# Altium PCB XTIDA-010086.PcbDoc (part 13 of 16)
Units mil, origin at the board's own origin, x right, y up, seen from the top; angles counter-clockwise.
Board outline 14763.78 x 8267.72 mil, 6 copper layers (Top Layer, GND Layer, Signal Layer 1, Signal Layer 2, Power Layer, Bottom Layer), stack 62 mil thick; 1933 components, 1002 nets, 4886 pads, 6482 vias.
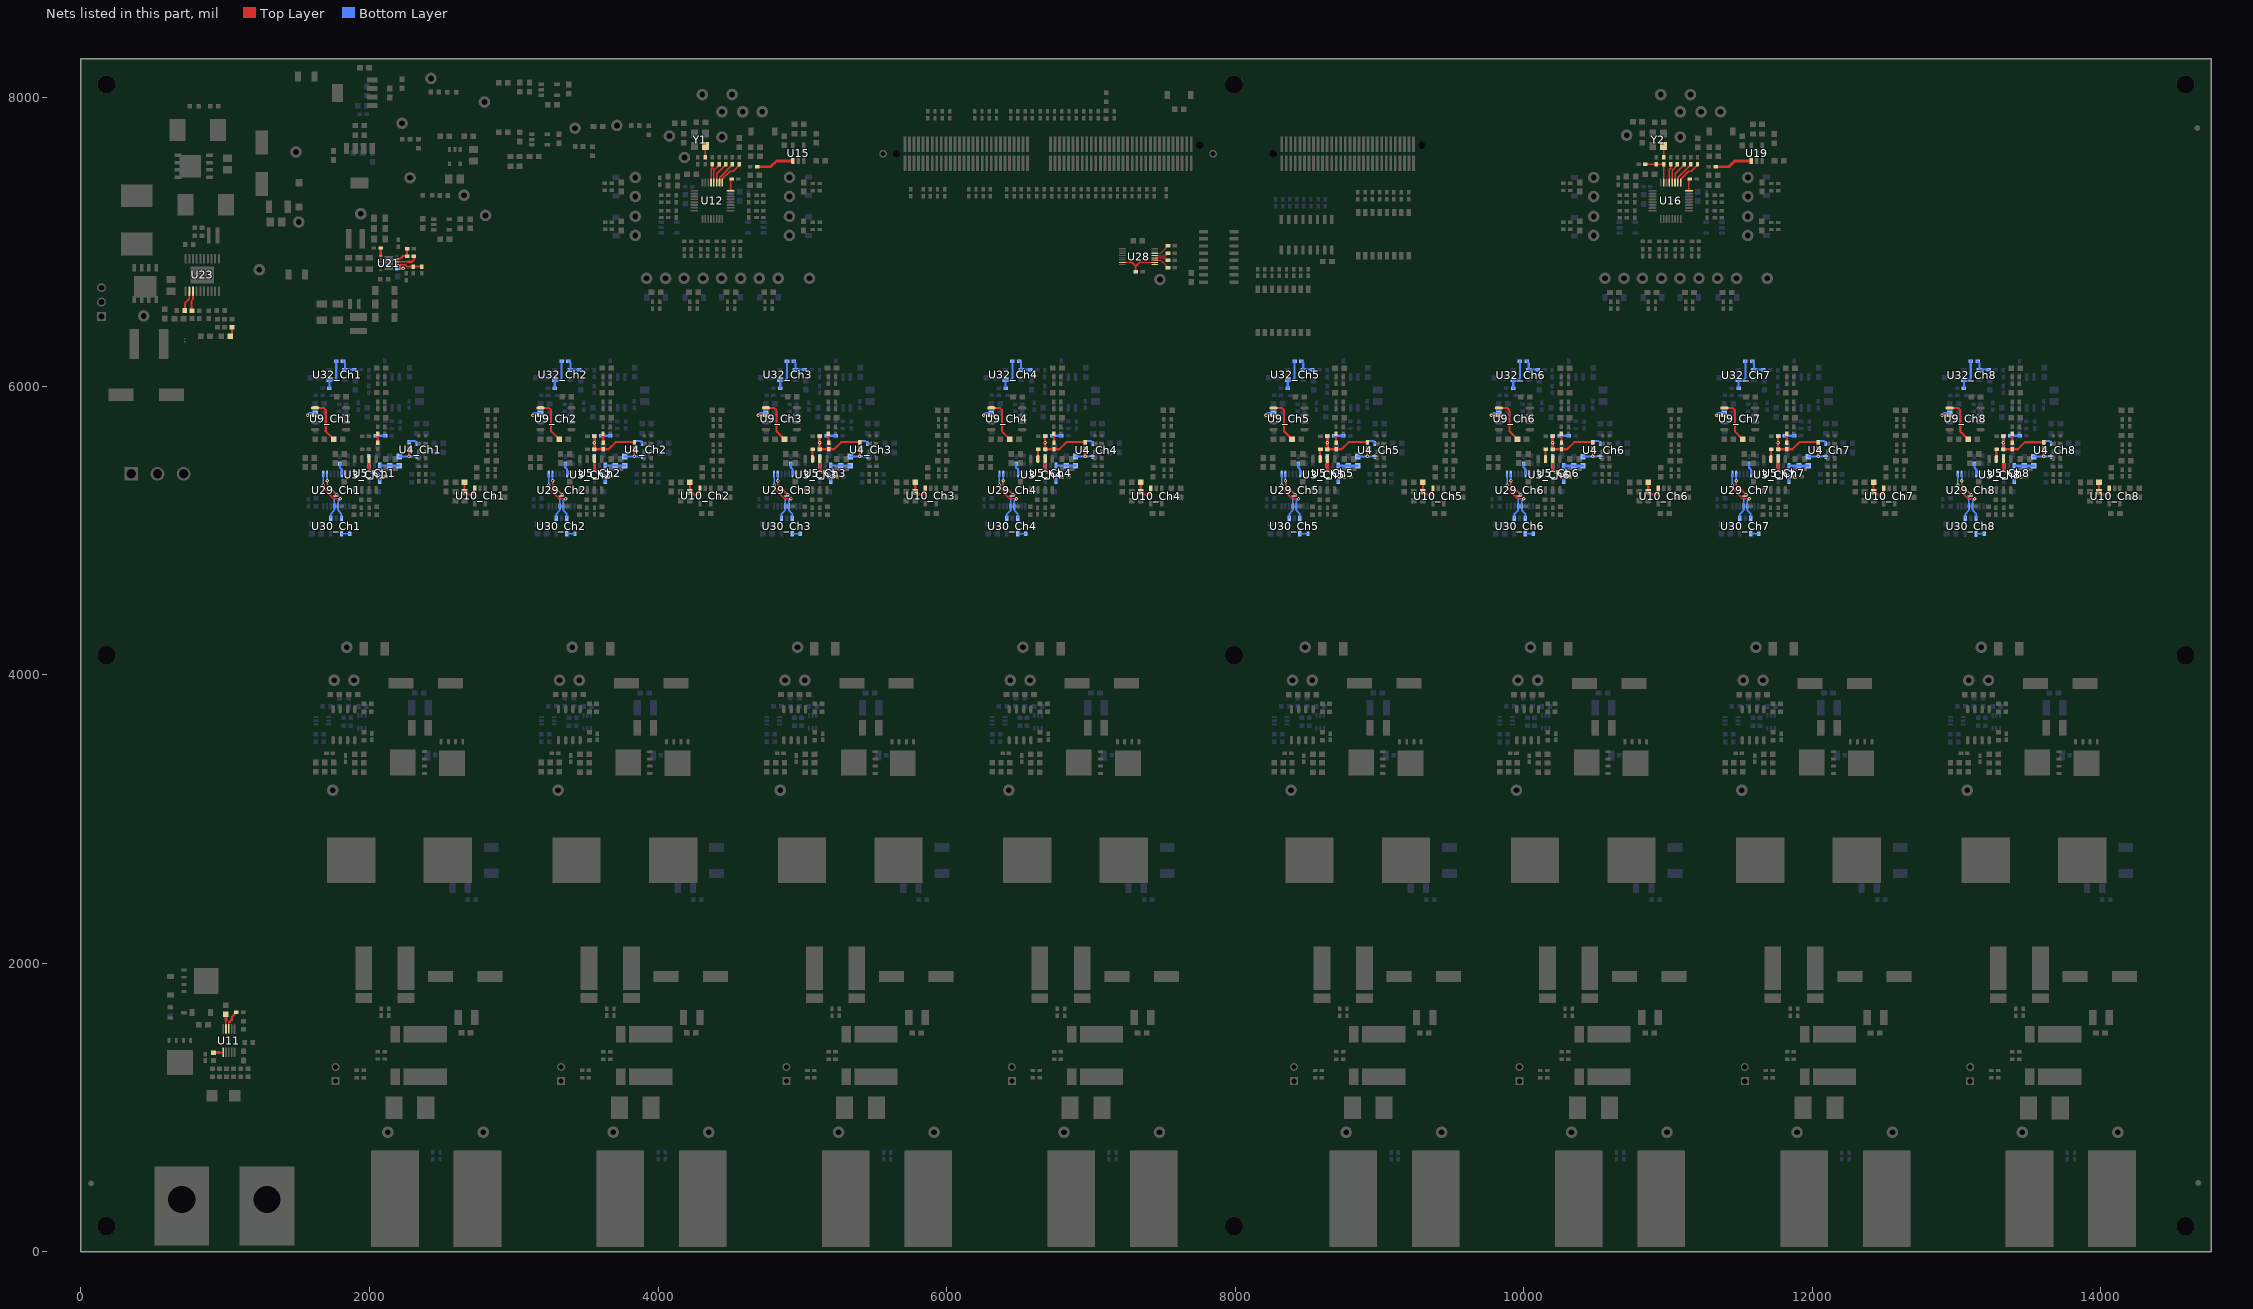
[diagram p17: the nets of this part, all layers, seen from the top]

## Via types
v1: diameter 32, hole 16, Top Layer to Bottom Layer, tented both sides, 4685 vias
v2: diameter 24, hole 12, Top Layer to Bottom Layer, tented both sides, 1013 vias
v3: diameter 32, hole 16, Top Layer to Bottom Layer, 728 vias
v4: diameter 19.68, hole 7.87, Top Layer to Bottom Layer, 40 vias
v5: diameter 214.57, hole 140, Top Layer to Bottom Layer, 16 vias

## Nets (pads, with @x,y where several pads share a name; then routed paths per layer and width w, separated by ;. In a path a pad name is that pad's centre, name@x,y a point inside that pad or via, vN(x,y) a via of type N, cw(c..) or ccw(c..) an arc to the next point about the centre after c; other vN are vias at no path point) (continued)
NetR31_Ch2_2: R31_Ch2.2 R32_Ch2.1 R41_Ch2.1 R43_Ch2.1 R48_Ch2.1 R175_Ch2.2 | length 484.6
  Top Layer w15: R31_Ch2.2@3558.62,5561.97 v2(3558.62,5607.62) R175_Ch2.2@3558.62,5653.28 ; R31_Ch2.2@3558.62,5561.97 3657.45,5562 3707.04,5611.59 R41_Ch2.1@3837,5611.59
  Bottom Layer w15: R43_Ch2.1@3558.62,5561.97 v2(3558.62,5607.62) 3558.62,5655.21 R48_Ch2.1@3559.38,5655.97
NetR31_Ch3_1: R31_Ch3.1 U3_Ch3.7 | length 68.7
  Top Layer w15: U3_Ch3.7@5071,5494.17 5071,5559.51 R31_Ch3.1@5073.38,5561.89
NetR31_Ch3_2: R31_Ch3.2 R32_Ch3.1 R41_Ch3.1 R43_Ch3.1 R48_Ch3.1 R175_Ch3.2 | length 481.4
  Top Layer w15: R175_Ch3.2@5120.62,5653.2 v2(5120.62,5607.54) R31_Ch3.2@5120.62,5561.89 5215.42,5561.89 ; R32_Ch3.1@5181.38,5561.89 R32_Ch3.1@5182,5561.27 ; 5219.45,5561.92 5269.04,5611.51 R41_Ch3.1@5399,5611.51
  Bottom Layer w15: R43_Ch3.1@5120.62,5561.89 v2(5120.62,5607.54) 5120.62,5655.13 R48_Ch3.1@5121.38,5655.89
NetR31_Ch4_1: R31_Ch4.1 U3_Ch4.7 | length 68.7
  Top Layer w15: U3_Ch4.7@6633,5494.09 6633,5559.43 R31_Ch4.1@6635.38,5561.81
NetR31_Ch4_2: R31_Ch4.2 R32_Ch4.1 R41_Ch4.1 R43_Ch4.1 R48_Ch4.1 R175_Ch4.2 | length 481.4
  Top Layer w15: R175_Ch4.2@6682.62,5653.12 v2(6682.62,5607.46) R31_Ch4.2@6682.62,5561.81 6777.42,5561.81 ; R32_Ch4.1@6743.38,5561.81 R32_Ch4.1@6744,5561.19 ; 6781.45,5561.84 6831.04,5611.43 R41_Ch4.1@6961,5611.43
  Bottom Layer w15: R43_Ch4.1@6682.62,5561.81 v2(6682.62,5607.46) 6682.62,5655.06 R48_Ch4.1@6683.38,5655.81
NetR31_Ch5_1: R31_Ch5.1 U3_Ch5.7 | length 68.7
  Top Layer w15: U3_Ch5.7@8588.7,5494.02 8588.7,5559.35 R31_Ch5.1@8591.08,5561.73
NetR31_Ch5_2: R31_Ch5.2 R32_Ch5.1 R41_Ch5.1 R43_Ch5.1 R48_Ch5.1 R175_Ch5.2 | length 481.4
  Top Layer w15: R175_Ch5.2@8638.32,5653.04 v2(8638.32,5607.39) R31_Ch5.2@8638.32,5561.73 8733.12,5561.73 ; R32_Ch5.1@8699.08,5561.73 R32_Ch5.1@8699.7,5561.11 ; 8737.15,5561.76 8786.74,5611.35 R41_Ch5.1@8916.7,5611.35
  Bottom Layer w15: R43_Ch5.1@8638.32,5561.73 v2(8638.32,5607.39) 8638.32,5654.98 R48_Ch5.1@8639.08,5655.73
NetR31_Ch6_1: R31_Ch6.1 U3_Ch6.7 | length 68.7
  Top Layer w15: U3_Ch6.7@10150.7,5493.94 10150.7,5559.28 R31_Ch6.1@10153.08,5561.65
NetR31_Ch6_2: R31_Ch6.2 R32_Ch6.1 R41_Ch6.1 R43_Ch6.1 R48_Ch6.1 R175_Ch6.2 | length 481.4
  Top Layer w15: R175_Ch6.2@10200.32,5652.96 v2(10200.32,5607.31) R31_Ch6.2@10200.32,5561.65 10295.12,5561.65 ; R32_Ch6.1@10261.08,5561.65 R32_Ch6.1@10261.7,5561.03 ; 10299.15,5561.68 10348.74,5611.28 R41_Ch6.1@10478.7,5611.28
  Bottom Layer w15: R43_Ch6.1@10200.32,5561.65 v2(10200.32,5607.31) 10200.32,5654.9 R48_Ch6.1@10201.08,5655.65
NetR31_Ch7_1: R31_Ch7.1 U3_Ch7.7 | length 68.7
  Top Layer w15: U3_Ch7.7@11712.7,5493.86 11712.7,5559.2 R31_Ch7.1@11715.08,5561.57
NetR31_Ch7_2: R31_Ch7.2 R32_Ch7.1 R41_Ch7.1 R43_Ch7.1 R48_Ch7.1 R175_Ch7.2 | length 481.4
  Top Layer w15: R175_Ch7.2@11762.32,5652.88 v2(11762.32,5607.23) R31_Ch7.2@11762.32,5561.57 11857.12,5561.57 ; R32_Ch7.1@11823.08,5561.57 R32_Ch7.1@11823.7,5560.95 ; 11861.15,5561.6 11910.74,5611.2 R41_Ch7.1@12040.7,5611.2
  Bottom Layer w15: R43_Ch7.1@11762.32,5561.57 v2(11762.32,5607.23) 11762.32,5654.82 R48_Ch7.1@11763.08,5655.57
NetR31_Ch8_1: R31_Ch8.1 U3_Ch8.7 | length 68.7
  Top Layer w15: U3_Ch8.7@13274.7,5493.78 13274.7,5559.12 R31_Ch8.1@13277.08,5561.5
NetR31_Ch8_2: R31_Ch8.2 R32_Ch8.1 R41_Ch8.1 R43_Ch8.1 R48_Ch8.1 R175_Ch8.2 | length 481.4
  Top Layer w15: R175_Ch8.2@13324.32,5652.8 v2(13324.32,5607.15) R31_Ch8.2@13324.32,5561.5 13419.12,5561.5 ; R32_Ch8.1@13385.08,5561.5 R32_Ch8.1@13385.7,5560.87 ; 13423.15,5561.52 13472.74,5611.12 R41_Ch8.1@13602.7,5611.12
  Bottom Layer w15: R43_Ch8.1@13324.32,5561.5 v2(13324.32,5607.15) 13324.32,5654.74 R48_Ch8.1@13325.08,5655.5
NetR32_Ch1_2: R32_Ch1.2 R33_Ch1.1 | length 62.2
  Top Layer w15: R33_Ch1.1@2057,5670.43 2058,5669.43 R32_Ch1.2@2058,5608.67
NetR32_Ch2_2: R32_Ch2.2 R33_Ch2.1 | length 62.2
  Top Layer w15: R33_Ch2.1@3619,5670.35 3620,5669.35 R32_Ch2.2@3620,5608.59
NetR32_Ch3_2: R32_Ch3.2 R33_Ch3.1 | length 62.2
  Top Layer w15: R33_Ch3.1@5181,5670.27 5182,5669.27 R32_Ch3.2@5182,5608.51
NetR32_Ch4_2: R32_Ch4.2 R33_Ch4.1 | length 62.2
  Top Layer w15: R33_Ch4.1@6743,5670.19 6744,5669.19 R32_Ch4.2@6744,5608.43
NetR32_Ch5_2: R32_Ch5.2 R33_Ch5.1 | length 62.2
  Top Layer w15: R33_Ch5.1@8698.7,5670.11 8699.7,5669.11 R32_Ch5.2@8699.7,5608.35
NetR32_Ch6_2: R32_Ch6.2 R33_Ch6.1 | length 62.2
  Top Layer w15: R33_Ch6.1@10260.7,5670.03 10261.7,5669.03 R32_Ch6.2@10261.7,5608.28
NetR32_Ch7_2: R32_Ch7.2 R33_Ch7.1 | length 62.2
  Top Layer w15: R33_Ch7.1@11822.7,5669.95 11823.7,5668.95 R32_Ch7.2@11823.7,5608.2
NetR32_Ch8_2: R32_Ch8.2 R33_Ch8.1 | length 62.2
  Top Layer w15: R33_Ch8.1@13384.7,5669.87 13385.7,5668.87 R32_Ch8.2@13385.7,5608.12
NetR41_Ch1_2: R41_Ch1.2 R44_Ch1.1 U4_Ch1.6 | length 171.1
  Top Layer w15: v2(2275,5513.28) R41_Ch1.2@2275,5564.43
  Bottom Layer w15: R44_Ch1.1@2207,5511.54 2325.2,5511.54 U4_Ch1.6@2326.41,5512.76
NetR41_Ch2_2: R41_Ch2.2 R44_Ch2.1 U4_Ch2.6 | length 171.1
  Top Layer w15: v2(3837,5513.21) R41_Ch2.2@3837,5564.35
  Bottom Layer w15: R44_Ch2.1@3769,5511.46 3887.2,5511.46 U4_Ch2.6@3888.41,5512.68
NetR41_Ch3_2: R41_Ch3.2 R44_Ch3.1 U4_Ch3.6 | length 171.1
  Top Layer w15: v2(5399,5513.13) R41_Ch3.2@5399,5564.27
  Bottom Layer w15: R44_Ch3.1@5331,5511.39 5449.2,5511.39 U4_Ch3.6@5450.41,5512.6
NetR41_Ch4_2: R41_Ch4.2 R44_Ch4.1 U4_Ch4.6 | length 171.1
  Top Layer w15: v2(6961,5513.05) R41_Ch4.2@6961,5564.19
  Bottom Layer w15: R44_Ch4.1@6893,5511.31 7011.2,5511.31 U4_Ch4.6@7012.41,5512.52
NetR41_Ch5_2: R41_Ch5.2 R44_Ch5.1 U4_Ch5.6 | length 171.1
  Top Layer w15: v2(8916.7,5512.97) R41_Ch5.2@8916.7,5564.11
  Bottom Layer w15: R44_Ch5.1@8848.7,5511.23 8966.9,5511.23 U4_Ch5.6@8968.11,5512.44
NetR41_Ch6_2: R41_Ch6.2 R44_Ch6.1 U4_Ch6.6 | length 171.1
  Top Layer w15: v2(10478.7,5512.89) R41_Ch6.2@10478.7,5564.03
  Bottom Layer w15: R44_Ch6.1@10410.7,5511.15 10528.9,5511.15 U4_Ch6.6@10530.11,5512.36
NetR41_Ch7_2: R41_Ch7.2 R44_Ch7.1 U4_Ch7.6 | length 171.1
  Top Layer w15: v2(12040.7,5512.81) R41_Ch7.2@12040.7,5563.95
  Bottom Layer w15: R44_Ch7.1@11972.7,5511.07 12090.9,5511.07 U4_Ch7.6@12092.11,5512.28
NetR41_Ch8_2: R41_Ch8.2 R44_Ch8.1 U4_Ch8.6 | length 171.1
  Top Layer w15: v2(13602.7,5512.73) R41_Ch8.2@13602.7,5563.87
  Bottom Layer w15: R44_Ch8.1@13534.7,5510.99 13652.9,5510.99 U4_Ch8.6@13654.11,5512.2
NetR42_1: R42.1 U28.7 U28.9 U28.10 | length 300.5
  Top Layer w6: U28.7@7218,6857.02 7261.44,6857.02 ; 7361.32,6857.02 U28.10@7442.41,6857.02 U28.9@7442.41,6841.27
  Top Layer w10: 7261.44,6857.02 7283.99,6857.02 7311.38,6829.63 ; R42.1@7311.38,6792.01 7311.38,6829.63 ; 7361.32,6857.02 7338.76,6857.02 7311.38,6829.63
NetR43_Ch1_2: R43_Ch1.2 U5_Ch1.1 U5_Ch1.4 | length 231.5
  Bottom Layer w15: R43_Ch1.2@1996.62,5514.8 1997.6,5513.83 U5_Ch1.1@1997.6,5449.18 1997.6,5413.08 2009.98,5400.7 2054.72,5400.7 2072.4,5383.02 U5_Ch1.4@2072.4,5340.91
NetR43_Ch2_2: R43_Ch2.2 U5_Ch2.1 U5_Ch2.4 | length 231.5
  Bottom Layer w15: R43_Ch2.2@3558.62,5514.72 3559.6,5513.75 U5_Ch2.1@3559.6,5449.1 3559.6,5413 3571.98,5400.62 3616.72,5400.62 3634.4,5382.94 U5_Ch2.4@3634.4,5340.83
NetR43_Ch3_2: R43_Ch3.2 U5_Ch3.1 U5_Ch3.4 | length 231.5
  Bottom Layer w15: R43_Ch3.2@5120.62,5514.65 5121.6,5513.67 U5_Ch3.1@5121.6,5449.02 5121.6,5412.92 5133.98,5400.54 5178.72,5400.54 5196.4,5382.87 U5_Ch3.4@5196.4,5340.76
NetR43_Ch4_2: R43_Ch4.2 U5_Ch4.1 U5_Ch4.4 | length 231.5
  Bottom Layer w15: R43_Ch4.2@6682.62,5514.57 6683.6,5513.59 U5_Ch4.1@6683.6,5448.94 6683.6,5412.84 6695.98,5400.46 6740.72,5400.46 6758.4,5382.79 U5_Ch4.4@6758.4,5340.68
NetR43_Ch5_2: R43_Ch5.2 U5_Ch5.1 U5_Ch5.4 | length 231.5
  Bottom Layer w15: R43_Ch5.2@8638.32,5514.49 8639.3,5513.51 U5_Ch5.1@8639.3,5448.87 8639.3,5412.76 8651.68,5400.39 8696.42,5400.39 8714.1,5382.71 U5_Ch5.4@8714.1,5340.6
NetR43_Ch6_2: R43_Ch6.2 U5_Ch6.1 U5_Ch6.4 | length 231.5
  Bottom Layer w15: R43_Ch6.2@10200.32,5514.41 10201.3,5513.43 U5_Ch6.1@10201.3,5448.79 10201.3,5412.69 10213.68,5400.31 10258.42,5400.31 10276.1,5382.63 U5_Ch6.4@10276.1,5340.52
NetR43_Ch7_2: R43_Ch7.2 U5_Ch7.1 U5_Ch7.4 | length 231.5
  Bottom Layer w15: R43_Ch7.2@11762.32,5514.33 11763.3,5513.35 11763.3,5412.61 11775.68,5400.23 11820.42,5400.23 11838.1,5382.55 U5_Ch7.4@11838.1,5340.44
NetR43_Ch8_2: R43_Ch8.2 U5_Ch8.1 U5_Ch8.4 | length 231.5
  Bottom Layer w15: R43_Ch8.2@13324.32,5514.25 13325.3,5513.28 13325.3,5412.53 13337.68,5400.15 13382.42,5400.15 13400.1,5382.47 U5_Ch8.4@13400.1,5340.36
NetR44_Ch1_2: R44_Ch1.2 R46_Ch1.2 U5_Ch1.3 | length 134.9
  Bottom Layer w15: U5_Ch1.3@2072.4,5449.18 2073.03,5448.55 R46_Ch1.2@2142,5448.55 R44_Ch1.2@2207,5448.55
NetR44_Ch2_2: R44_Ch2.2 R46_Ch2.2 U5_Ch2.3 | length 134.9
  Bottom Layer w15: U5_Ch2.3@3634.4,5449.1 3635.03,5448.47 R46_Ch2.2@3704,5448.47 R44_Ch2.2@3769,5448.47
NetR44_Ch3_2: R44_Ch3.2 R46_Ch3.2 U5_Ch3.3 | length 134.9
  Bottom Layer w15: U5_Ch3.3@5196.4,5449.02 5197.03,5448.39 R46_Ch3.2@5266,5448.39 R44_Ch3.2@5331,5448.39
NetR44_Ch4_2: R44_Ch4.2 R46_Ch4.2 U5_Ch4.3 | length 134.9
  Bottom Layer w15: U5_Ch4.3@6758.4,5448.94 6759.03,5448.32 R46_Ch4.2@6828,5448.32 R44_Ch4.2@6893,5448.32
NetR44_Ch5_2: R44_Ch5.2 R46_Ch5.2 U5_Ch5.3 | length 134.9
  Bottom Layer w15: U5_Ch5.3@8714.1,5448.87 8714.73,5448.24 R46_Ch5.2@8783.7,5448.24 R44_Ch5.2@8848.7,5448.24
NetR44_Ch6_2: R44_Ch6.2 R46_Ch6.2 U5_Ch6.3 | length 134.9
  Bottom Layer w15: U5_Ch6.3@10276.1,5448.79 10276.73,5448.16 R46_Ch6.2@10345.7,5448.16 R44_Ch6.2@10410.7,5448.16
NetR44_Ch7_2: R44_Ch7.2 R46_Ch7.2 U5_Ch7.3 | length 134.9
  Bottom Layer w15: U5_Ch7.3@11838.1,5448.71 11838.73,5448.08 R46_Ch7.2@11907.7,5448.08 R44_Ch7.2@11972.7,5448.08
NetR44_Ch8_2: R44_Ch8.2 R46_Ch8.2 U5_Ch8.3 | length 134.9
  Bottom Layer w15: U5_Ch8.3@13400.1,5448.63 13400.73,5448 R46_Ch8.2@13469.7,5448 R44_Ch8.2@13534.7,5448
NetR48_Ch1_2: R48_Ch1.2 R52_Ch1.1 | length 63.8
  Bottom Layer w15: R48_Ch1.2@2044.62,5656.05 R52_Ch1.1@2108.38,5656.05
NetR48_Ch2_2: R48_Ch2.2 R52_Ch2.1 | length 63.8
  Bottom Layer w15: R48_Ch2.2@3606.62,5655.97 R52_Ch2.1@3670.38,5655.97
NetR48_Ch3_2: R48_Ch3.2 R52_Ch3.1 | length 63.8
  Bottom Layer w15: R48_Ch3.2@5168.62,5655.89 R52_Ch3.1@5232.38,5655.89
NetR48_Ch4_2: R48_Ch4.2 R52_Ch4.1 | length 63.8
  Bottom Layer w15: R48_Ch4.2@6730.62,5655.81 R52_Ch4.1@6794.38,5655.81
NetR48_Ch5_2: R48_Ch5.2 R52_Ch5.1 | length 63.8
  Bottom Layer w15: R48_Ch5.2@8686.32,5655.73 R52_Ch5.1@8750.08,5655.73
NetR48_Ch6_2: R48_Ch6.2 R52_Ch6.1 | length 63.8
  Bottom Layer w15: R48_Ch6.2@10248.32,5655.65 R52_Ch6.1@10312.08,5655.65
NetR48_Ch7_2: R48_Ch7.2 R52_Ch7.1 | length 63.8
  Bottom Layer w15: R48_Ch7.2@11810.32,5655.57 R52_Ch7.1@11874.08,5655.57
NetR48_Ch8_2: R48_Ch8.2 R52_Ch8.1 | length 63.8
  Bottom Layer w15: R48_Ch8.2@13372.32,5655.5 R52_Ch8.1@13436.08,5655.5
NetR49_Ch1_1: R49_Ch1.1 U4_Ch1.1 | length 64.9
  Bottom Layer w15: R49_Ch1.1@2275,5611.67 2282.03,5618.7 2314.79,5618.7 2326.41,5607.08 U4_Ch1.1@2326.41,5601.34
NetR49_Ch2_1: R49_Ch2.1 U4_Ch2.1 | length 64.9
  Bottom Layer w15: R49_Ch2.1@3837,5611.59 3844.03,5618.62 3876.79,5618.62 3888.41,5607 U4_Ch2.1@3888.41,5601.26
NetR49_Ch3_1: R49_Ch3.1 U4_Ch3.1 | length 64.9
  Bottom Layer w15: R49_Ch3.1@5399,5611.51 5406.03,5618.54 5438.79,5618.54 5450.41,5606.92 U4_Ch3.1@5450.41,5601.18
NetR49_Ch4_1: R49_Ch4.1 U4_Ch4.1 | length 64.9
  Bottom Layer w15: R49_Ch4.1@6961,5611.43 6968.03,5618.46 7000.79,5618.46 7012.41,5606.84 U4_Ch4.1@7012.41,5601.1
NetR49_Ch5_1: R49_Ch5.1 U4_Ch5.1 | length 64.9
  Bottom Layer w15: R49_Ch5.1@8916.7,5611.35 8923.73,5618.39 8956.49,5618.39 8968.11,5606.76 U4_Ch5.1@8968.11,5601.02
NetR49_Ch6_1: R49_Ch6.1 U4_Ch6.1 | length 64.9
  Bottom Layer w15: R49_Ch6.1@10478.7,5611.28 10485.73,5618.31 10518.49,5618.31 10530.11,5606.69 U4_Ch6.1@10530.11,5600.94
NetR49_Ch7_1: R49_Ch7.1 U4_Ch7.1 | length 64.9
  Bottom Layer w15: R49_Ch7.1@12040.7,5611.2 12047.73,5618.23 12080.49,5618.23 12092.11,5606.61 U4_Ch7.1@12092.11,5600.87
NetR49_Ch8_1: R49_Ch8.1 U4_Ch8.1 | length 64.9
  Bottom Layer w15: R49_Ch8.1@13602.7,5611.12 13609.73,5618.15 13642.49,5618.15 13654.11,5606.53 U4_Ch8.1@13654.11,5600.79
NetR54_1: R54.1 U28.14 | length 113.1
  Top Layer w6: U28.14@7442.41,6920.01 7483.38,6920.01 R54.1@7534.38,6971.01
NetR55_1: R55.1 U28.13 | length 98.9
  Top Layer w6: U28.13@7442.41,6904.26 7517.63,6904.26 R55.1@7534.38,6921.01
NetR56_1: R56.1 U28.12 | length 99.2
  Top Layer w6: U28.12@7442.41,6888.52 7516.87,6888.52 R56.1@7534.38,6871.01
NetR57_1: R57.1 U28.11 | length 113.4
  Top Layer w6: U28.11@7442.41,6872.77 7482.62,6872.77 R57.1@7534.38,6821.01
NetR63_Ch1_1: R63_Ch1.1 R64_Ch1.2 U10_Ch1.3 | length 182
  Top Layer w15: R63_Ch1.1@2659.04,5332.68 R64_Ch1.2@2659.04,5268.3 2667.02,5268.3 2687.18,5248.14 2720.47,5248.14 2729.14,5256.82 U10_Ch1.3@2729.14,5292.43
NetR63_Ch2_1: R63_Ch2.1 R64_Ch2.2 U10_Ch2.3 | length 182
  Top Layer w15: R63_Ch2.1@4221.04,5332.6 R64_Ch2.2@4221.04,5268.22 4229.02,5268.22 4249.18,5248.06 4282.47,5248.06 4291.14,5256.74 U10_Ch2.3@4291.14,5292.35
NetR63_Ch3_1: R63_Ch3.1 R64_Ch3.2 U10_Ch3.3 | length 182
  Top Layer w15: R63_Ch3.1@5783.04,5332.52 R64_Ch3.2@5783.04,5268.14 5791.02,5268.14 5811.18,5247.98 5844.47,5247.98 5853.14,5256.66 U10_Ch3.3@5853.14,5292.28
NetR63_Ch4_1: R63_Ch4.1 R64_Ch4.2 U10_Ch4.3 | length 182
  Top Layer w15: R63_Ch4.1@7345.04,5332.44 R64_Ch4.2@7345.04,5268.06 7353.02,5268.06 7373.18,5247.91 7406.47,5247.91 7415.14,5256.58 U10_Ch4.3@7415.14,5292.2
NetR63_Ch5_1: R63_Ch5.1 R64_Ch5.2 U10_Ch5.3 | length 182
  Top Layer w15: R63_Ch5.1@9300.74,5332.36 R64_Ch5.2@9300.74,5267.98 9308.72,5267.98 9328.88,5247.83 9362.17,5247.83 9370.84,5256.5 U10_Ch5.3@9370.84,5292.12
NetR63_Ch6_1: R63_Ch6.1 R64_Ch6.2 U10_Ch6.3 | length 182
  Top Layer w15: R63_Ch6.1@10862.74,5332.28 R64_Ch6.2@10862.74,5267.91 10870.72,5267.91 10890.88,5247.75 10924.17,5247.75 10932.84,5256.42 U10_Ch6.3@10932.84,5292.04
NetR63_Ch7_1: R63_Ch7.1 R64_Ch7.2 U10_Ch7.3 | length 182
  Top Layer w15: R63_Ch7.1@12424.74,5332.2 R64_Ch7.2@12424.74,5267.83 12432.72,5267.83 12452.88,5247.67 12486.17,5247.67 12494.84,5256.34 U10_Ch7.3@12494.84,5291.96
NetR63_Ch8_1: R63_Ch8.1 R64_Ch8.2 U10_Ch8.3 | length 182
  Top Layer w15: R63_Ch8.1@13986.74,5332.13 R64_Ch8.2@13986.74,5267.75 13994.72,5267.75 14014.88,5247.59 14048.17,5247.59 14056.84,5256.26 U10_Ch8.3@14056.84,5291.88
NetR75_Ch1_2: R75_Ch1.2 U9_Ch1.5 | length 305.1
  Top Layer w15: U9_Ch1.5@1623.72,5848.55 1681.61,5848.55 1697,5833.16 1697,5686.2 R75_Ch1.2@1752.5,5630.7
NetR75_Ch2_2: R75_Ch2.2 U9_Ch2.5 | length 305.1
  Top Layer w15: U9_Ch2.5@3185.72,5848.47 3243.61,5848.47 3259,5833.08 3259,5686.13 R75_Ch2.2@3314.5,5630.62
NetR75_Ch3_2: R75_Ch3.2 U9_Ch3.5 | length 305.1
  Top Layer w15: U9_Ch3.5@4747.72,5848.39 4805.61,5848.39 4821,5833 4821,5686.05 R75_Ch3.2@4876.5,5630.54
NetR75_Ch4_2: R75_Ch4.2 U9_Ch4.5 | length 305.1
  Top Layer w15: U9_Ch4.5@6309.72,5848.31 6367.61,5848.31 6383,5832.92 6383,5685.97 R75_Ch4.2@6438.5,5630.46
NetR75_Ch5_2: R75_Ch5.2 U9_Ch5.5 | length 305.1
  Top Layer w15: U9_Ch5.5@8265.42,5848.24 8323.31,5848.24 8338.7,5832.84 8338.7,5685.89 R75_Ch5.2@8394.2,5630.39
NetR75_Ch6_2: R75_Ch6.2 U9_Ch6.5 | length 305.1
  Top Layer w15: U9_Ch6.5@9827.42,5848.16 9885.31,5848.16 9900.7,5832.76 9900.7,5685.81 R75_Ch6.2@9956.2,5630.31
NetR75_Ch7_2: R75_Ch7.2 U9_Ch7.5 | length 305.1
  Top Layer w15: U9_Ch7.5@11389.42,5848.08 11447.31,5848.08 11462.7,5832.69 11462.7,5685.73 R75_Ch7.2@11518.2,5630.23
NetR75_Ch8_2: R75_Ch8.2 U9_Ch8.5 | length 305.1
  Top Layer w15: U9_Ch8.5@12951.42,5848 13009.31,5848 13024.7,5832.61 13024.7,5685.65 R75_Ch8.2@13080.2,5630.15
NetR78_Ch1_1: R78_Ch1.1 U9_Ch1.6 | length 111.1
  Top Layer w15: v2(1571.15,5798.55) U9_Ch1.6@1623.72,5798.55
  Bottom Layer w15: v2(1571.15,5798.55) 1585.63,5813.03 R78_Ch1.1@1623.72,5813.03
NetR78_Ch2_1: R78_Ch2.1 U9_Ch2.6 | length 111.1
  Top Layer w15: v2(3133.15,5798.47) U9_Ch2.6@3185.72,5798.47
  Bottom Layer w15: v2(3133.15,5798.47) 3147.63,5812.95 R78_Ch2.1@3185.72,5812.95
NetR78_Ch3_1: R78_Ch3.1 U9_Ch3.6 | length 111.1
  Top Layer w15: v2(4695.15,5798.39) U9_Ch3.6@4747.72,5798.39
  Bottom Layer w15: v2(4695.15,5798.39) 4709.63,5812.87 R78_Ch3.1@4747.72,5812.87
NetR78_Ch4_1: R78_Ch4.1 U9_Ch4.6 | length 111.1
  Top Layer w15: v2(6257.15,5798.31) U9_Ch4.6@6309.72,5798.31
  Bottom Layer w15: v2(6257.15,5798.31) 6271.63,5812.79 R78_Ch4.1@6309.72,5812.79
NetR78_Ch5_1: R78_Ch5.1 U9_Ch5.6 | length 111.1
  Top Layer w15: v2(8212.85,5798.24) U9_Ch5.6@8265.42,5798.24
  Bottom Layer w15: v2(8212.85,5798.24) 8227.33,5812.71 R78_Ch5.1@8265.42,5812.71
NetR78_Ch6_1: R78_Ch6.1 U9_Ch6.6 | length 111.1
  Top Layer w15: v2(9774.85,5798.16) U9_Ch6.6@9827.42,5798.16
  Bottom Layer w15: v2(9774.85,5798.16) 9789.33,5812.63 R78_Ch6.1@9827.42,5812.63
NetR78_Ch7_1: R78_Ch7.1 U9_Ch7.6 | length 111.1
  Top Layer w15: v2(11336.85,5798.08) U9_Ch7.6@11389.42,5798.08
  Bottom Layer w15: v2(11336.85,5798.08) 11351.33,5812.55 R78_Ch7.1@11389.42,5812.55
NetR78_Ch8_1: R78_Ch8.1 U9_Ch8.6 | length 111.1
  Top Layer w15: v2(12898.85,5798) U9_Ch8.6@12951.42,5798
  Bottom Layer w15: v2(12898.85,5798) 12913.33,5812.48 R78_Ch8.1@12951.42,5812.48
NetR82_2: R82.2 U11.1 | length 67.4
  Top Layer w10: 961.37,1381.12 984.01,1381.12 U11.1@985.96,1383.07
  Top Layer w20: R82.2@919.33,1381.12 961.37,1381.12
NetR83_1: R83.1 U11.9 | length 101.3
  Top Layer w10: U11.9@1005.65,1544.48 1005.65,1604
  Top Layer w20: R83.1@1005,1645.5 1005.65,1644.86 1005.65,1604
NetR86_1: R86.1 U11.8 | length 136.1
  Top Layer w10: U11.8@1025.33,1544.48 1025.33,1588.04 1032.14,1594.86
  Top Layer w15: 1032.14,1594.86 1047.14,1609.86 1047.14,1628.77 R86.1@1077.38,1659
NetR97_2: R97.2 Y1.3 | length 78.2
  Top Layer w10: R97.2@4328.11,7584.63 4328.11,7662.3 Y1.3@4328.52,7662.7
NetR102_1: R102.1 U12.21 | length 131.1
  Top Layer w10: U12.21@4367.27,7410 4367.27,7501.38 4376.11,7510.22 R102.1@4376.11,7537.39
NetR105_1: R105.1 U12.20 | length 142.4
  Top Layer w10: U12.20@4386.96,7410 4386.96,7495.79 4423.11,7531.94 R105.1@4423.11,7537.39
NetR106_1: R106.1 U12.19 | length 153.3
  Top Layer w10: U12.19@4406.64,7410 4406.64,7471.54 4469.11,7534.01 R106.1@4469.11,7537.39
NetR110_1: R110.1 U12.18 | length 164.2
  Top Layer w10: U12.18@4426.33,7410 4426.33,7444.43 4515.11,7533.22 R110.1@4515.11,7537.39
NetR112_1: R112.1 U12.17 | length 187.2
  Top Layer w10: U12.17@4446.01,7410 4446.01,7435.12 4500.53,7489.63 4520.53,7489.63 4562.11,7531.22 R112.1@4562.11,7537.39
NetR114_1: R114.1 U12.16 | length 84.8
  Top Layer w10: U12.16@4503.1,7352.91 4503.1,7428.62 R114.1@4509.49,7435.01
NetR120_1: R120.1 U15.1 | length 263.9
  Top Layer w20: R120.1@4687.74,7520.01 4779.91,7520.01 4820.24,7560.35 U15.1@4934.93,7560.35
NetR126_1: R126.1 R128.1 R187.1 U16.23 | length 254.8
  Top Layer w10: R187.1@10842.62,7536.86 10842.83,7537.08 R126.1@10916.82,7537.08 R128.1@10969.82,7537.08 10969.6,7536.86 U16.23@10969.6,7409.68
NetR128_2: R128.2 Y2.3 | length 78.2
  Top Layer w10: R128.2@10969.82,7584.32 10969.82,7661.99 Y2.3@10970.22,7662.39
NetR133_1: R133.1 U16.21 | length 131.1
  Top Layer w10: U16.21@11008.97,7409.68 11008.97,7501.06 11017.82,7509.91 R133.1@11017.82,7537.08
NetR136_1: R136.1 U16.20 | length 142.4
  Top Layer w10: U16.20@11028.66,7409.68 11028.66,7495.47 11064.82,7531.63 R136.1@11064.82,7537.08
NetR137_1: R137.1 U16.19 | length 153.3
  Top Layer w10: U16.19@11048.34,7409.68 11048.34,7471.22 11110.82,7533.7 R137.1@11110.82,7537.08
NetR141_1: R141.1 U16.18 | length 164.2
  Top Layer w10: U16.18@11068.03,7409.68 11068.03,7444.12 11156.82,7532.91 R141.1@11156.82,7537.08
NetR143_1: R143.1 U16.17 | length 187.2
  Top Layer w10: U16.17@11087.71,7409.68 11087.71,7434.8 11142.23,7489.32 11162.23,7489.32 11203.82,7530.91 R143.1@11203.82,7537.08
NetR145_1: R145.1 U16.16 | length 84.8
  Top Layer w10: U16.16@11144.8,7352.59 11144.8,7428.3 R145.1@11151.19,7434.7
NetR151_1: R151.1 U19.1 | length 264
  Top Layer w20: R151.1@11329.44,7519.7 11421.61,7519.7 11461.94,7560.03 U19.1@11576.63,7560.03
NetR160_Ch1_1: R160_Ch1.1 U30_Ch1.4 | length 56.8
  Bottom Layer w10: U30_Ch1.4@1806.4,4975.87 1862.49,4975.87 R160_Ch1.1@1863,4976.38
NetR160_Ch2_1: R160_Ch2.1 U30_Ch2.4 | length 56.8
  Bottom Layer w10: U30_Ch2.4@3368.4,4975.79 R160_Ch2.1@3424.49,4975.79 R160_Ch2.1@3425,4976.3
NetR160_Ch3_1: R160_Ch3.1 U30_Ch3.4 | length 56.8
  Bottom Layer w10: U30_Ch3.4@4930.4,4975.71 R160_Ch3.1@4986.49,4975.71 R160_Ch3.1@4987,4976.22
NetR160_Ch4_1: R160_Ch4.1 U30_Ch4.4 | length 56.8
  Bottom Layer w10: U30_Ch4.4@6492.4,4975.63 6548.49,4975.63 R160_Ch4.1@6549,4976.14
NetR160_Ch5_1: R160_Ch5.1 U30_Ch5.4 | length 56.8
  Bottom Layer w10: U30_Ch5.4@8448.1,4975.55 8504.19,4975.55 R160_Ch5.1@8504.7,4976.06
NetR160_Ch6_1: R160_Ch6.1 U30_Ch6.4 | length 56.8
  Bottom Layer w10: U30_Ch6.4@10010.1,4975.47 10066.19,4975.47 R160_Ch6.1@10066.7,4975.98
NetR160_Ch7_1: R160_Ch7.1 U30_Ch7.4 | length 56.8
  Bottom Layer w10: U30_Ch7.4@11572.1,4975.39 11628.19,4975.39 R160_Ch7.1@11628.7,4975.91
NetR160_Ch8_1: R160_Ch8.1 U30_Ch8.4 | length 56.8
  Bottom Layer w10: U30_Ch8.4@13134.1,4975.32 R160_Ch8.1@13190.19,4975.32 R160_Ch8.1@13190.7,4975.83
NetR161_Ch1_2: R161_Ch1.2 U29_Ch1.6 | length 76.2
  Bottom Layer w15: R161_Ch1.2@1795.38,5462 1795.38,5435.62 1808.39,5422.61 U29_Ch1.6@1808.39,5391.2
NetR161_Ch2_2: R161_Ch2.2 U29_Ch2.6 | length 76.2
  Bottom Layer w15: R161_Ch2.2@3357.38,5461.92 3357.38,5435.54 3370.39,5422.54 U29_Ch2.6@3370.39,5391.13
NetR161_Ch3_2: R161_Ch3.2 U29_Ch3.6 | length 76.2
  Bottom Layer w15: R161_Ch3.2@4919.38,5461.84 4919.38,5435.46 4932.39,5422.46 U29_Ch3.6@4932.39,5391.05
NetR161_Ch4_2: R161_Ch4.2 U29_Ch4.6 | length 76.2
  Bottom Layer w15: R161_Ch4.2@6481.38,5461.76 6481.38,5435.39 6494.39,5422.38 U29_Ch4.6@6494.39,5390.97
NetR161_Ch5_2: R161_Ch5.2 U29_Ch5.6 | length 76.2
  Bottom Layer w15: R161_Ch5.2@8437.08,5461.69 8437.08,5435.31 8450.09,5422.3 U29_Ch5.6@8450.09,5390.89
NetR161_Ch6_2: R161_Ch6.2 U29_Ch6.6 | length 76.2
  Bottom Layer w15: R161_Ch6.2@9999.08,5461.61 9999.08,5435.23 10012.09,5422.22 U29_Ch6.6@10012.09,5390.81
NetR161_Ch7_2: R161_Ch7.2 U29_Ch7.6 | length 76.2
  Bottom Layer w15: R161_Ch7.2@11561.08,5461.53 11561.08,5435.15 11574.09,5422.14 U29_Ch7.6@11574.09,5390.73
NetR161_Ch8_2: R161_Ch8.2 U29_Ch8.6 | length 76.2
  Bottom Layer w15: R161_Ch8.2@13123.08,5461.45 13123.08,5435.07 13136.09,5422.06 U29_Ch8.6@13136.09,5390.65
NetR185_Ch1_2: R185_Ch1.2 U3_Ch1.6 | length 203.7
  Top Layer w20: U3_Ch1.6@1997,5494.33 1997,5429 2053,5373 R185_Ch1.2@2112.17,5373
NetR185_Ch2_2: R185_Ch2.2 U3_Ch2.6 | length 203.7
  Top Layer w20: U3_Ch2.6@3559,5494.25 3559,5428.92 3615,5372.92 R185_Ch2.2@3674.17,5372.92
NetR185_Ch3_2: R185_Ch3.2 U3_Ch3.6 | length 203.7
  Top Layer w20: U3_Ch3.6@5121,5494.17 5121,5428.84 5177,5372.84 R185_Ch3.2@5236.17,5372.84
NetR185_Ch4_2: R185_Ch4.2 U3_Ch4.6 | length 203.7
  Top Layer w20: U3_Ch4.6@6683,5494.09 6683,5428.76 6739,5372.76 R185_Ch4.2@6798.17,5372.76
NetR185_Ch5_2: R185_Ch5.2 U3_Ch5.6 | length 203.7
  Top Layer w20: U3_Ch5.6@8638.7,5494.02 8638.7,5428.69 8694.7,5372.69 R185_Ch5.2@8753.87,5372.69
NetR185_Ch6_2: R185_Ch6.2 U3_Ch6.6 | length 203.7
  Top Layer w20: U3_Ch6.6@10200.7,5493.94 10200.7,5428.61 10256.7,5372.61 R185_Ch6.2@10315.87,5372.61
NetR185_Ch7_2: R185_Ch7.2 U3_Ch7.6 | length 203.7
  Top Layer w20: U3_Ch7.6@11762.7,5493.86 11762.7,5428.53 11818.7,5372.53 R185_Ch7.2@11877.87,5372.53
NetR185_Ch8_2: R185_Ch8.2 U3_Ch8.6 | length 203.7
  Top Layer w20: U3_Ch8.6@13324.7,5493.78 13324.7,5428.45 13380.7,5372.45 R185_Ch8.2@13439.87,5372.45
NetR195_2: R195.2 U21.2 | length 90.1
  Top Layer w10: U21.2@2189.12,6822.46 2211.28,6822.46 2218.74,6815 v2(2235,6815)
  Bottom Layer w15: R195.2@2197,6822.5 2204.5,6815 v2(2235,6815)
NetR196_2: R196.2 U21.7 | length 55.5
  Top Layer w15: U21.7@2078.62,6901.46 R196.2@2078.62,6957
NetR197_1: R197.1 R199.2 U21.5 | length 130.3
  Top Layer w10: U21.5@2189.12,6881.51 2213.51,6881.51 2224,6892
  Top Layer w15: 2224,6892 2233,6901 R197.1@2261.38,6901 R199.2@2261.38,6951
NetR197_2: R197.2 U21.4 | length 150.6
  Top Layer w10: U21.4@2189.12,6861.83 2268,6861.83
  Top Layer w15: 2268,6861.83 2294.83,6861.83 2308.62,6875.62 R197.2@2308.62,6901
NetR204_Ch1_1: R204_Ch1.1 R219_Ch1.1 U32_Ch1.1 | length 227.6
  Bottom Layer w15: R219_Ch1.1@1722.62,5985 1722.62,6039.08 U32_Ch1.1@1721.87,6039.83 1754.83,6039.83 1769.62,6054.62 R204_Ch1.1@1769.62,6173.24
NetR204_Ch1_2: R204_Ch1.2 R218_Ch1.1 U32_Ch1.4 | length 127.3
  Bottom Layer w15: R204_Ch1.2@1816.87,6173.24 1830.13,6159.97 U32_Ch1.4@1830.13,6114.64 R218_Ch1.1@1893.35,6114.64
NetR204_Ch2_1: R204_Ch2.1 R219_Ch2.1 U32_Ch2.1 | length 227.6
  Bottom Layer w15: R219_Ch2.1@3284.87,5984.68 3284.87,6038.76 U32_Ch2.1@3284.11,6039.51 3317.08,6039.51 3331.87,6054.3 R204_Ch2.1@3331.87,6172.91
NetR204_Ch2_2: R204_Ch2.2 R218_Ch2.1 U32_Ch2.4 | length 127.3
  Bottom Layer w15: R204_Ch2.2@3379.11,6172.91 3392.38,6159.65 U32_Ch2.4@3392.38,6114.31 R218_Ch2.1@3455.6,6114.31
NetR204_Ch3_1: R204_Ch3.1 R219_Ch3.1 U32_Ch3.1 | length 227.6
  Bottom Layer w15: R219_Ch3.1@4846.87,5984.6 4846.87,6038.68 4846.11,6039.43 4879.08,6039.43 4893.87,6054.22 R204_Ch3.1@4893.87,6172.83
NetR204_Ch3_2: R204_Ch3.2 R218_Ch3.1 U32_Ch3.4 | length 127.3
  Bottom Layer w15: R204_Ch3.2@4939.22,6173.31 4952.49,6160.04 U32_Ch3.4@4952.49,6114.71 R218_Ch3.1@5015.71,6114.71
NetR204_Ch4_1: R204_Ch4.1 R219_Ch4.1 U32_Ch4.1 | length 227.6
  Bottom Layer w15: R219_Ch4.1@6408.87,5984.52 6408.87,6038.6 U32_Ch4.1@6408.11,6039.35 6441.08,6039.35 6455.87,6054.14 R204_Ch4.1@6455.87,6172.76
NetR204_Ch4_2: R204_Ch4.2 R218_Ch4.1 U32_Ch4.4 | length 127.3
  Bottom Layer w15: R204_Ch4.2@6503.11,6172.76 6516.38,6159.49 U32_Ch4.4@6516.38,6114.16 R218_Ch4.1@6579.6,6114.16
NetR204_Ch5_1: R204_Ch5.1 R219_Ch5.1 U32_Ch5.1 | length 227.6
  Bottom Layer w15: R219_Ch5.1@8364.57,5984.44 8364.57,6038.52 U32_Ch5.1@8363.81,6039.28 8396.78,6039.28 8411.57,6054.06 R204_Ch5.1@8411.57,6172.68
NetR204_Ch5_2: R204_Ch5.2 R218_Ch5.1 U32_Ch5.4 | length 127.4
  Bottom Layer w15: R204_Ch5.2@8458.81,6172.68 8472.08,6159.41 U32_Ch5.4@8472.08,6114.08 R218_Ch5.1@8535.38,6114 R218_Ch5.1@8535.38,6114
NetR204_Ch6_1: R204_Ch6.1 R219_Ch6.1 U32_Ch6.1 | length 227.6
  Bottom Layer w15: R219_Ch6.1@9926.57,5984.36 U32_Ch6.1@9926.57,6038.44 9925.81,6039.2 9958.78,6039.2 9973.57,6053.98 R204_Ch6.1@9973.57,6172.6
NetR204_Ch6_2: R204_Ch6.2 R218_Ch6.1 U32_Ch6.4 | length 127.4
  Bottom Layer w15: R204_Ch6.2@10020.81,6172.6 10034.08,6159.33 10034.08,6114 10097.3,6114 R218_Ch6.1@10097.38,6113.92
NetR204_Ch7_1: R204_Ch7.1 R219_Ch7.1 U32_Ch7.1 | length 227.6
  Bottom Layer w15: R219_Ch7.1@11488.57,5984.28 11488.57,6038.36 U32_Ch7.1@11487.81,6039.12 11520.78,6039.12 11535.57,6053.91 R204_Ch7.1@11535.57,6172.52
NetR204_Ch7_2: R204_Ch7.2 R218_Ch7.1 U32_Ch7.4 | length 127.4
  Bottom Layer w15: R204_Ch7.2@11582.81,6172.52 11596.08,6159.25 U32_Ch7.4@11596.08,6113.92 R218_Ch7.1@11659.3,6113.92 R218_Ch7.1@11659.38,6113.84
NetR204_Ch8_1: R204_Ch8.1 R219_Ch8.1 U32_Ch8.1 | length 227.6
  Bottom Layer w15: R219_Ch8.1@13050.57,5984.2 13050.57,6038.28 U32_Ch8.1@13049.81,6039.04 13082.78,6039.04 13097.57,6053.83 R204_Ch8.1@13097.57,6172.44
NetR204_Ch8_2: R204_Ch8.2 R218_Ch8.1 U32_Ch8.4 | length 127.4
  Bottom Layer w15: R204_Ch8.2@13144.81,6172.44 13158.08,6159.17 U32_Ch8.4@13158.08,6113.84 R218_Ch8.1@13221.3,6113.84 R218_Ch8.1@13221.38,6113.76
NetR206_2: R206.2 U23.2 | length 145.6
  Top Layer w12: R206.2@721.06,6524.7 721.06,6573.45 751.94,6604.32 U23.2@751.94,6657.5
NetR210_2: R210.2 U23.3 | length 152.2
  Top Layer w12: R210.2@771.3,6523.46 777.53,6529.69 766.54,6529.69 766.54,6590.81 777.53,6601.8 U23.3@777.53,6657.5
NetR214_2: R214.2 R215.1 | length 67.8
  Top Layer w15: R214.2@1035,6345.7 1047.5,6358.2 R215.1@1047.5,6408.34
NetU29_Ch1_1: U29_Ch1.1 U29_Ch1.12 U30_Ch1.3 | length 396.8
  Top Layer w10: v2(1681,5314) 1681,5291 1753,5219 v2(1797,5219)
  Bottom Layer w10: U29_Ch1.1@1680.43,5391.2 1680.43,5314.57 v2(1681,5314) ; v2(1797,5219) 1782.8,5204.8 U29_Ch1.12@1782.8,5166.8 1782.8,5138.2 1806.4,5114.6 U30_Ch1.3@1806.4,5084.13
NetU29_Ch1_2: U29_Ch1.2 U29_Ch1.13 U30_Ch1.1 | length 353.6
  Top Layer w10: v2(1707,5344) 1707,5314 v2(1775,5246)
  Bottom Layer w10: U29_Ch1.2@1706.02,5391.2 1706.02,5344.98 v2(1707,5344) ; U30_Ch1.1@1731.6,5084.13 1731.6,5112.6 1757.2,5138.2 U29_Ch1.13@1757.2,5166.8 1757.2,5228.2 v2(1775,5246)
NetU29_Ch2_1: U29_Ch2.1 U29_Ch2.12 U30_Ch2.3 | length 397.9
  Top Layer w10: v2(3243,5313.92) 3243,5290.92 3315,5218.92 v2(3359,5218.92)
  Bottom Layer w10: U29_Ch2.1@3242.43,5391.13 3242.43,5314.49 v2(3243,5313.92) ; U29_Ch2.12@3344.02,5165.94 U29_Ch2.12@3344.8,5166.72 ; v2(3359,5218.92) 3344.8,5204.72 U29_Ch2.12@3344.8,5166.72 ; U30_Ch2.3@3368.4,5084.06 3368.4,5114.52 3344.8,5138.13 U29_Ch2.12@3344.8,5166.72
NetU29_Ch2_2: U29_Ch2.2 U29_Ch2.13 U30_Ch2.1 | length 353.6
  Top Layer w10: v2(3269,5343.92) 3269,5313.92 v2(3337,5245.92)
  Bottom Layer w10: U29_Ch2.2@3268.02,5391.13 3268.02,5344.9 v2(3269,5343.92) ; U30_Ch2.1@3293.6,5084.06 3293.6,5112.52 3319.2,5138.13 U29_Ch2.13@3319.2,5166.72 3319.2,5228.13 v2(3337,5245.92)
NetU29_Ch3_1: U29_Ch3.1 U29_Ch3.12 U30_Ch3.3 | length 397.9
  Top Layer w10: v2(4805,5313.84) 4805,5290.84 4877,5218.84 v2(4921,5218.84)
  Bottom Layer w10: U29_Ch3.1@4804.43,5391.05 4804.43,5314.41 v2(4805,5313.84) ; U29_Ch3.12@4906.02,5165.87 U29_Ch3.12@4906.8,5166.64 ; v2(4921,5218.84) 4906.8,5204.64 U29_Ch3.12@4906.8,5166.64 ; U30_Ch3.3@4930.4,5083.98 4930.4,5114.44 4906.8,5138.05 U29_Ch3.12@4906.8,5166.64
NetU29_Ch3_2: U29_Ch3.2 U29_Ch3.13 U30_Ch3.1 | length 353.6
  Top Layer w10: v2(4831,5343.84) 4831,5313.84 v2(4899,5245.84)
  Bottom Layer w10: U29_Ch3.2@4830.02,5391.05 4830.02,5344.82 v2(4831,5343.84) ; U30_Ch3.1@4855.6,5083.98 4855.6,5112.44 4881.2,5138.05 U29_Ch3.13@4881.2,5166.64 4881.2,5228.05 v2(4899,5245.84)
NetU29_Ch4_1: U29_Ch4.1 U29_Ch4.12 U30_Ch4.3 | length 397.9
  Top Layer w10: v2(6367,5313.76) 6367,5290.76 6439,5218.76 v2(6483,5218.76)
  Bottom Layer w10: U29_Ch4.1@6366.43,5390.97 6366.43,5314.33 v2(6367,5313.76) ; U29_Ch4.12@6468.02,5165.79 U29_Ch4.12@6468.8,5166.56 ; v2(6483,5218.76) 6468.8,5204.56 U29_Ch4.12@6468.8,5166.56 ; U30_Ch4.3@6492.4,5083.9 6492.4,5114.36 6468.8,5137.97 U29_Ch4.12@6468.8,5166.56
NetU29_Ch4_2: U29_Ch4.2 U29_Ch4.13 U30_Ch4.1 | length 353.6
  Top Layer w10: v2(6393,5343.76) 6393,5313.76 v2(6461,5245.76)
  Bottom Layer w10: U29_Ch4.2@6392.02,5390.97 6392.02,5344.74 v2(6393,5343.76) ; U30_Ch4.1@6417.6,5083.9 6417.6,5112.36 6443.2,5137.97 U29_Ch4.13@6443.2,5166.56 6443.2,5227.97 v2(6461,5245.76)
NetU29_Ch5_1: U29_Ch5.1 U29_Ch5.12 U30_Ch5.3 | length 397.9
  Top Layer w10: v2(8322.7,5313.69) 8322.7,5290.69 8394.7,5218.69 v2(8438.7,5218.69)
  Bottom Layer w10: U29_Ch5.1@8322.13,5390.89 8322.13,5314.25 v2(8322.7,5313.69) ; U29_Ch5.12@8423.72,5165.71 U29_Ch5.12@8424.5,5166.48 ; v2(8438.7,5218.69) 8424.5,5204.48 U29_Ch5.12@8424.5,5166.48 ; U30_Ch5.3@8448.1,5083.82 8448.1,5114.28 8424.5,5137.89 U29_Ch5.12@8424.5,5166.48
NetU29_Ch5_2: U29_Ch5.2 U29_Ch5.13 U30_Ch5.1 | length 353.6
  Top Layer w10: v2(8348.7,5343.69) 8348.7,5313.69 v2(8416.7,5245.69)
  Bottom Layer w10: U29_Ch5.2@8347.72,5390.89 8347.72,5344.66 v2(8348.7,5343.69) ; U30_Ch5.1@8373.3,5083.82 8373.3,5112.28 8398.91,5137.89 U29_Ch5.13@8398.91,5166.48 8398.91,5227.89 v2(8416.7,5245.69)
NetU29_Ch6_1: U29_Ch6.1 U29_Ch6.12 U30_Ch6.3 | length 399
  Top Layer w10: v2(9884.7,5313.61) 9884.7,5290.61 9956.7,5218.61 v2(10000.7,5218.61)
  Bottom Layer w10: U29_Ch6.1@9884.13,5390.81 9884.13,5314.17 v2(9884.7,5313.61) ; v2(10000.7,5218.61) 9986.5,5204.4 U29_Ch6.12@9986.5,5166.4 ; U30_Ch6.3@10010.1,5083.74 10010.1,5114.21 9986.5,5137.81 U29_Ch6.12@9986.5,5166.4 ; U29_Ch6.12@9986.5,5166.4 9985.72,5165.63 U29_Ch6.12@9986.5,5166.4
NetU29_Ch6_2: U29_Ch6.2 U29_Ch6.13 U30_Ch6.1 | length 353.6
  Top Layer w10: v2(9910.7,5343.61) 9910.7,5313.61 v2(9978.7,5245.61)
  Bottom Layer w10: U29_Ch6.2@9909.72,5390.81 9909.72,5344.58 v2(9910.7,5343.61) ; U30_Ch6.1@9935.3,5083.74 9935.3,5112.2 9960.91,5137.81 U29_Ch6.13@9960.91,5166.4 9960.91,5227.81 v2(9978.7,5245.61)
NetU29_Ch7_1: U29_Ch7.1 U29_Ch7.12 U30_Ch7.3 | length 399
  Top Layer w10: v2(11446.7,5313.53) 11446.7,5290.53 11518.7,5218.53 v2(11562.7,5218.53)
  Bottom Layer w10: U29_Ch7.1@11446.13,5390.73 11446.13,5314.09 v2(11446.7,5313.53) ; v2(11562.7,5218.53) 11548.5,5204.32 U29_Ch7.12@11548.5,5166.32 ; U30_Ch7.3@11572.1,5083.66 11572.1,5114.13 11548.5,5137.73 U29_Ch7.12@11548.5,5166.32 ; U29_Ch7.12@11548.5,5166.32 11547.72,5165.55 U29_Ch7.12@11548.5,5166.32
NetU29_Ch7_2: U29_Ch7.2 U29_Ch7.13 U30_Ch7.1 | length 353.6
  Top Layer w10: v2(11472.7,5343.53) 11472.7,5313.53 v2(11540.7,5245.53)
  Bottom Layer w10: U29_Ch7.2@11471.72,5390.73 11471.72,5344.5 v2(11472.7,5343.53) ; U30_Ch7.1@11497.3,5083.66 11497.3,5112.13 11522.91,5137.73 U29_Ch7.13@11522.91,5166.32 11522.91,5227.73 v2(11540.7,5245.53)
NetU29_Ch8_1: U29_Ch8.1 U29_Ch8.12 U30_Ch8.3 | length 399
  Top Layer w10: v2(13008.7,5313.45) 13008.7,5290.45 13080.7,5218.45 v2(13124.7,5218.45)
  Bottom Layer w10: U29_Ch8.1@13008.13,5390.65 13008.13,5314.02 v2(13008.7,5313.45) ; v2(13124.7,5218.45) 13110.5,5204.24 U29_Ch8.12@13110.5,5166.24 ; U30_Ch8.3@13134.1,5083.58 13134.1,5114.05 13110.5,5137.65 U29_Ch8.12@13110.5,5166.24 ; U29_Ch8.12@13110.5,5166.24 13109.72,5165.47 U29_Ch8.12@13110.5,5166.24
NetU29_Ch8_2: U29_Ch8.2 U29_Ch8.13 U30_Ch8.1 | length 353.6
  Top Layer w10: v2(13034.7,5343.45) 13034.7,5313.45 v2(13102.7,5245.45)
  Bottom Layer w10: U29_Ch8.2@13033.72,5390.65 13033.72,5344.43 v2(13034.7,5343.45) ; U30_Ch8.1@13059.3,5083.58 13059.3,5112.05 13084.91,5137.65 U29_Ch8.13@13084.91,5166.24 13084.91,5227.65 v2(13102.7,5245.45)
"OVP: 14.4V": C57.2 R85.1 R89.2 U11.3 | length 217.5
  Top Layer w10: 1014,1332 1025.33,1343.33 U11.3@1025.33,1383.07
  Top Layer w15: R85.1@912.04,1269.32 R89.2@960.54,1269.32 C57.2@1009.04,1269.32 1009.04,1327.04 1014,1332
PG_-5V: R198.1 R200.1 U21.3 | length 178.9
  Top Layer w10: U21.3@2189.12,6842.14 2247.55,6842.14 2262.07,6827.62 2278,6827.62
  Top Layer w15: 2278,6827.62 R198.1@2305,6827.62 R200.1@2362,6827.62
